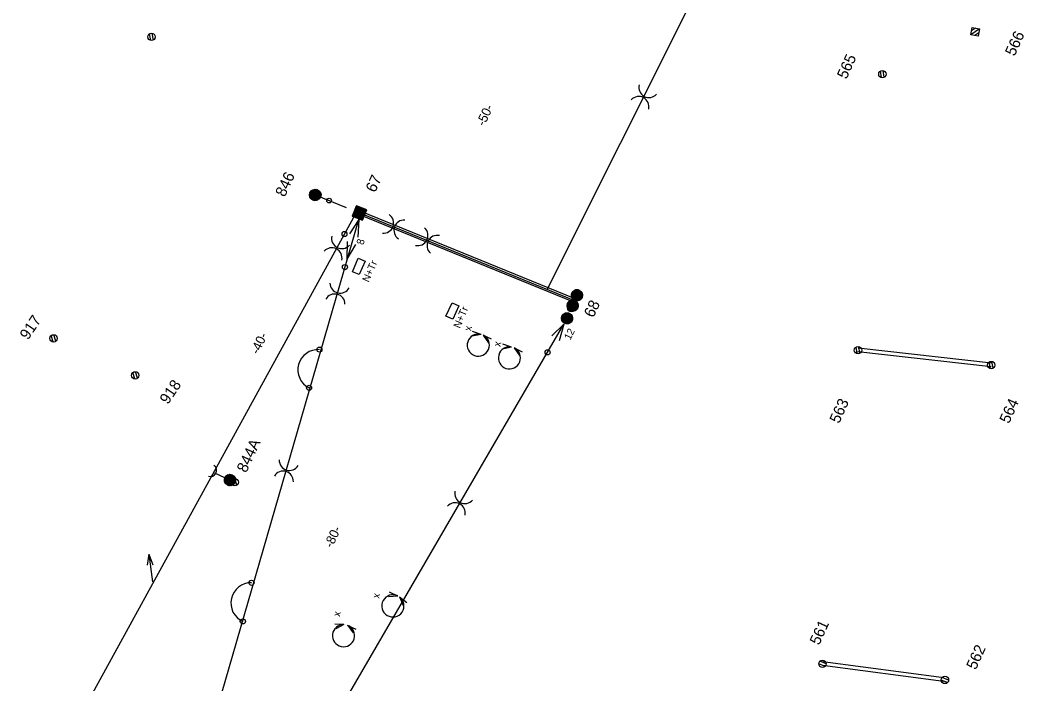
# Model space of a CAD drawing. Extents: x -595867 to -593796, y -1159595 to -1157495.
# Drawn here: x -594787.7 to -594651.8, y -1158117.2 to -1158027.2 of the extents above; entities that cross this region are included whole.
import ezdxf

# ---------------------------------------------------------------- set-up
doc = ezdxf.new("R2010")
doc.units = 0
for name, color, linetype in [('BVK_kanalizace_destova_nova', 7, 'Continuous'), ('BVK_kanalizace_jednotna_nova', 7, 'Continuous'), ('CD Telematika_novy', 7, 'Continuous')]:
    doc.layers.add(name, color=color, linetype=linetype)

# ---------------------------------------------------------------- blocks, each defined once
blk = doc.blocks.new('st_bp')
for p, q in [((0.0075, 0.0075), (-0.0075, 0.0075)), ((-0.0075, 0.0075), (-0.0075, -0.0075)), ((-0.0075, -0.0075), (0.0075, 0.0075)), ((-0.0075, -0.0071), (0.0071, 0.0075)), ((-0.0075, -0.0067), (0.0067, 0.0075)), ((-0.0075, -0.0062), (0.0062, 0.0075)), ((-0.0075, -0.0058), (0.0058, 0.0075)), ((-0.0075, -0.0054), (0.0054, 0.0075)), ((-0.0075, -0.005), (0.005, 0.0075)), ((-0.0075, -0.0045), (0.0045, 0.0075)), ((-0.0075, -0.0041), (0.0041, 0.0075)), ((-0.0075, -0.0037), (0.0037, 0.0075)), ((-0.0075, -0.0033), (0.0033, 0.0075)), ((-0.0075, -0.0028), (0.0028, 0.0075)), ((-0.0075, -0.0024), (0.0024, 0.0075)), ((-0.0075, -0.002), (0.002, 0.0075)), ((-0.0075, -0.0016), (0.0016, 0.0075)), ((-0.0075, -0.0011), (0.0011, 0.0075)), ((-0.0075, -0.0007), (0.0007, 0.0075)), ((-0.0075, -0.0003), (0.0003, 0.0075)), ((-0.0075, 0.0001), (-0.0001, 0.0075)), ((-0.0075, 0.0006), (-0.0006, 0.0075)), ((-0.0075, 0.001), (-0.001, 0.0075)), ((-0.0075, 0.0014), (-0.0014, 0.0075)), ((-0.0075, 0.0018), (-0.0018, 0.0075)), ((-0.0075, 0.0023), (-0.0023, 0.0075)), ((-0.0075, 0.0027), (-0.0027, 0.0075)), ((-0.0075, 0.0031), (-0.0031, 0.0075)), ((-0.0075, 0.0035), (-0.0035, 0.0075)), ((-0.0075, 0.004), (-0.004, 0.0075)), ((-0.0075, 0.0044), (-0.0044, 0.0075)), ((-0.0075, 0.0048), (-0.0048, 0.0075)), ((-0.0075, 0.0052), (-0.0052, 0.0075)), ((-0.0075, 0.0057), (-0.0057, 0.0075)), ((-0.0075, 0.0061), (-0.0061, 0.0075)), ((-0.0075, 0.0065), (-0.0065, 0.0075)), ((-0.0075, 0.0069), (-0.0069, 0.0075)), ((-0.0075, 0.0073), (-0.0073, 0.0075)), ((-0.0071, -0.0075), (0.0075, 0.0071)), ((-0.0067, -0.0075), (0.0075, 0.0067)), ((-0.0062, -0.0075), (0.0075, 0.0062)), ((-0.0058, -0.0075), (0.0075, 0.0058)), ((-0.0054, -0.0075), (0.0075, 0.0054)), ((-0.005, -0.0075), (0.0075, 0.005)), ((-0.0045, -0.0075), (0.0075, 0.0045)), ((-0.0041, -0.0075), (0.0075, 0.0041)), ((-0.0037, -0.0075), (0.0075, 0.0037)), ((-0.0033, -0.0075), (0.0075, 0.0033)), ((-0.0028, -0.0075), (0.0075, 0.0028)), ((-0.0024, -0.0075), (0.0075, 0.0024)), ((-0.002, -0.0075), (0.0075, 0.002)), ((-0.0016, -0.0075), (0.0075, 0.0016)), ((-0.0011, -0.0075), (0.0075, 0.0011)), ((-0.0007, -0.0075), (0.0075, 0.0007)), ((-0.0003, -0.0075), (0.0075, 0.0003)), ((0.0075, -0.0075), (0.0075, 0.0075)), ((-0.0075, -0.0075), (0.0075, -0.0075)), ((0.0001, -0.0075), (0.0075, -0.0001)), ((0.0006, -0.0075), (0.0075, -0.0006)), ((0.001, -0.0075), (0.0075, -0.001)), ((0.0014, -0.0075), (0.0075, -0.0014)), ((0.0018, -0.0075), (0.0075, -0.0018)), ((0.0023, -0.0075), (0.0075, -0.0023)), ((0.0027, -0.0075), (0.0075, -0.0027)), ((0.0031, -0.0075), (0.0075, -0.0031)), ((0.0035, -0.0075), (0.0075, -0.0035)), ((0.004, -0.0075), (0.0075, -0.004)), ((0.0044, -0.0075), (0.0075, -0.0044)), ((0.0048, -0.0075), (0.0075, -0.0048)), ((0.0052, -0.0075), (0.0075, -0.0052)), ((0.0057, -0.0075), (0.0075, -0.0057)), ((0.0061, -0.0075), (0.0075, -0.0061)), ((0.0065, -0.0075), (0.0075, -0.0065)), ((0.0069, -0.0075), (0.0075, -0.0069)), ((0.0073, -0.0075), (0.0075, -0.0073))]:
    blk.add_line(p, q)
blk = doc.blocks.new('st_tecka')
blk.add_circle((0, 0), 0.00314)
blk = doc.blocks.new('st_1t')
for points in [[(-0.0074, 0.0007), (0.0028, 0.0069), (0.0036, 0.0066), (-0.0075, -0.0002)], [(-0.0075, -0.0002), (0.0036, 0.0066), (0.0044, 0.006), (-0.0074, -0.001)], [(-0.0073, 0.0016), (0.0019, 0.0072), (0.0028, 0.0069), (-0.0074, 0.0007)], [(-0.0074, -0.001), (0.0044, 0.006), (0.0052, 0.0054), (-0.0072, -0.0019)], [(-0.0071, 0.0022), (0.0006, 0.0074), (0.0019, 0.0072), (-0.0073, 0.0016)], [(-0.0072, -0.0019), (0.0052, 0.0054), (0.0059, 0.0046), (-0.0069, -0.003)], [(-0.0069, 0.0029), (-0.0001, 0.0075), (0.0006, 0.0074), (-0.0071, 0.0022)], [(-0.0067, 0.0033), (-0.0015, 0.0073), (-0.0001, 0.0075), (-0.0069, 0.0029)], [(-0.0069, -0.003), (0.0059, 0.0046), (0.0067, 0.0034), (-0.0064, -0.0039)], [(-0.0063, 0.004), (-0.0022, 0.0071), (-0.0015, 0.0073), (-0.0067, 0.0033)], [(-0.0064, -0.0039), (0.0067, 0.0034), (0.0071, 0.0022), (-0.0057, -0.0049)], [(-0.0058, 0.0047), (-0.0032, 0.0068), (-0.0022, 0.0071), (-0.0063, 0.004)], [(-0.0053, 0.0053), (-0.0041, 0.0062), (-0.0032, 0.0068), (-0.0058, 0.0047)], [(-0.0057, -0.0049), (0.0071, 0.0022), (0.0074, 0.0011), (-0.0049, -0.0056)], [(-0.0049, -0.0056), (0.0074, 0.0011), (0.0075, -0.0004), (-0.004, -0.0063)], [(-0.004, -0.0063), (0.0075, -0.0004), (0.0073, -0.0017), (-0.0032, -0.0068)], [(-0.0032, -0.0068), (0.0073, -0.0017), (0.007, -0.0027), (-0.0021, -0.0072)], [(-0.0021, -0.0072), (0.007, -0.0027), (0.0065, -0.0037), (-0.0011, -0.0074)], [(-0.0011, -0.0074), (0.0065, -0.0037), (0.0059, -0.0046), (-0.0005, -0.0075)], [(-0.0005, -0.0075), (0.0059, -0.0046), (0.0054, -0.0052), (0.0004, -0.0075)], [(0.0004, -0.0075), (0.0054, -0.0052), (0.0045, -0.006), (0.0014, -0.0074)], [(0.0014, -0.0074), (0.0045, -0.006), (0.0038, -0.0064), (0.0025, -0.007)], [(0.0025, -0.007), (0.0038, -0.0064), (0.0029, -0.0069), (0.0029, -0.0069)]]:
    blk.add_lwpolyline(points, close=True)
blk.add_circle((0, 0), 0.0075)
blk = doc.blocks.new('st1k_1t')
blk.add_line((0, 0), (0.0453, 0))
blk.add_blockref('st_1t', (0, 0))
at = {"rotation": 90}
blk.add_blockref('st_tecka', (0.0205, 0), dxfattribs=at)
blk = doc.blocks.new('st_2t')
for points in [[(-0.0077, 0.0091), (0.0015, 0.0147), (0.0025, 0.0144), (-0.0078, 0.0082)], [(-0.0078, 0.0082), (0.0025, 0.0144), (0.0032, 0.014), (-0.0078, 0.0072)], [(-0.0078, 0.0072), (0.0032, 0.014), (0.004, 0.0135), (-0.0078, 0.0065)], [(-0.0075, 0.0097), (0.0002, 0.0149), (0.0015, 0.0147), (-0.0077, 0.0091)], [(-0.0073, 0.0104), (-0.0005, 0.015), (0.0002, 0.0149), (-0.0075, 0.0097)], [(-0.0071, 0.0108), (-0.0019, 0.0148), (-0.0005, 0.015), (-0.0073, 0.0104)], [(-0.0066, 0.0115), (-0.0026, 0.0146), (-0.0019, 0.0148), (-0.0071, 0.0108)], [(-0.0062, 0.0122), (-0.0035, 0.0142), (-0.0026, 0.0146), (-0.0066, 0.0115)], [(-0.0056, 0.0128), (-0.0045, 0.0137), (-0.0035, 0.0142), (-0.0062, 0.0122)], [(-0.0078, 0.0065), (0.004, 0.0135), (0.0048, 0.0129), (-0.0076, 0.0056)], [(-0.0076, 0.0056), (0.0048, 0.0129), (0.0055, 0.0121), (-0.0073, 0.0044)], [(-0.0073, 0.0044), (0.0055, 0.0121), (0.0063, 0.0109), (-0.0068, 0.0036)], [(-0.0068, 0.0036), (0.0063, 0.0109), (0.0067, 0.0097), (-0.006, 0.0026)], [(-0.006, 0.0026), (0.0067, 0.0097), (0.007, 0.0086), (-0.0052, 0.0018)], [(-0.0052, 0.0018), (0.007, 0.0086), (0.0071, 0.0071), (-0.0044, 0.0012)], [(-0.0044, 0.0012), (0.0071, 0.0071), (0.0069, 0.0057), (-0.0035, 0.0007)], [(-0.0035, 0.0007), (0.0069, 0.0057), (0.0066, 0.0047), (-0.0024, 0.0003)], [(-0.0024, 0.0003), (0.0066, 0.0047), (0.0061, 0.0038), (-0.0015, 0.0001)], [(-0.0015, 0.0001), (0.0061, 0.0038), (0.0055, 0.0029), (-0.0009, 0)], [(-0.0009, 0), (0.0055, 0.0029), (0.005, 0.0022), (0, 0)], [(0, 0), (0.005, 0.0022), (0.0041, 0.0015), (0.001, 0.0001)], [(0.001, 0.0001), (0.0041, 0.0015), (0.0035, 0.001), (0.0021, 0.0004)], [(0.0021, 0.0004), (0.0035, 0.001), (0.0026, 0.0006), (0.0026, 0.0005)], [(-0.0077, -0.0059), (0.0015, -0.0003), (0.0025, -0.0006), (-0.0078, -0.0068)], [(-0.0078, -0.0068), (0.0025, -0.0006), (0.0032, -0.001), (-0.0078, -0.0078)], [(-0.0078, -0.0078), (0.0032, -0.001), (0.004, -0.0015), (-0.0078, -0.0085)], [(-0.0078, -0.0085), (0.004, -0.0015), (0.0048, -0.0021), (-0.0076, -0.0094)], [(-0.0075, -0.0053), (0.0002, -0.0001), (0.0015, -0.0003), (-0.0077, -0.0059)], [(-0.0076, -0.0094), (0.0048, -0.0021), (0.0055, -0.0029), (-0.0073, -0.0106)], [(-0.0073, -0.0046), (-0.0005, 0), (0.0002, -0.0001), (-0.0075, -0.0053)], [(-0.0071, -0.0042), (-0.0019, -0.0002), (-0.0005, 0), (-0.0073, -0.0046)], [(-0.0073, -0.0106), (0.0055, -0.0029), (0.0063, -0.0041), (-0.0068, -0.0114)], [(-0.0066, -0.0035), (-0.0026, -0.0004), (-0.0019, -0.0002), (-0.0071, -0.0042)], [(-0.0068, -0.0114), (0.0063, -0.0041), (0.0067, -0.0053), (-0.006, -0.0124)], [(-0.0062, -0.0028), (-0.0035, -0.0008), (-0.0026, -0.0004), (-0.0066, -0.0035)], [(-0.0056, -0.0022), (-0.0045, -0.0013), (-0.0035, -0.0008), (-0.0062, -0.0028)], [(-0.006, -0.0124), (0.0067, -0.0053), (0.007, -0.0064), (-0.0052, -0.0132)], [(-0.0052, -0.0132), (0.007, -0.0064), (0.0071, -0.0079), (-0.0044, -0.0138)], [(-0.0044, -0.0138), (0.0071, -0.0079), (0.0069, -0.0093), (-0.0035, -0.0143)], [(-0.0035, -0.0143), (0.0069, -0.0093), (0.0066, -0.0103), (-0.0024, -0.0147)], [(-0.0024, -0.0147), (0.0066, -0.0103), (0.0061, -0.0112), (-0.0015, -0.0149)], [(-0.0015, -0.0149), (0.0061, -0.0112), (0.0055, -0.0121), (-0.0009, -0.015)], [(-0.0009, -0.015), (0.0055, -0.0121), (0.005, -0.0128), (0, -0.015)], [(0, -0.015), (0.005, -0.0128), (0.0041, -0.0135), (0.001, -0.0149)], [(0.001, -0.0149), (0.0041, -0.0135), (0.0035, -0.014), (0.0021, -0.0146)], [(0.0021, -0.0146), (0.0035, -0.014), (0.0026, -0.0144), (0.0026, -0.0145)]]:
    blk.add_lwpolyline(points, close=True)
for centre in [(-0.0004, 0.0075), (-0.0004, -0.0075)]:
    blk.add_circle(centre, 0.0075)
blk = doc.blocks.new('pol_izol')
for centre, start, end in [((-0.0148, 0), 284.4047, 75.5953), ((0.0148, 0), 104.4047, 255.5953)]:
    blk.add_arc(centre, 0.0138, start, end)
blk = doc.blocks.new('kotv_tecka')
blk.add_circle((0, 0), 0.00345)
blk = doc.blocks.new('kotv_polok')
for p, q in [((-0.0558, 0), (-0.0328, 0.0065)), ((-0.0558, 0), (-0.0336, -0.0056)), ((0, 0), (-0.023, -0.0056))]:
    blk.add_line(p, q)
blk.add_lwpolyline([(0, 0), (-0.0221, 0.0064)])
blk.add_blockref('kotv_tecka', (-0.067, 0))
blk = doc.blocks.new('pol_proplan')
blk.add_arc((0.0268, -0.0054), 0.0274, 11.4341, 168.5659)
for p in [(0, 0), (0.0536, 0)]:
    blk.add_blockref('kotv_tecka', p)
blk = doc.blocks.new('kotv_pev')
blk.add_line((0, 0), (-0.023, -0.0056))
blk.add_lwpolyline([(0, 0), (-0.0221, 0.0064)])
blk.add_blockref('kotv_tecka', (-0.0442, 0))
blk = doc.blocks.new('pol_pevbod')
for q in [(0, 0), (0.0163, 0.0168), (0.0204, 0.0101)]:
    blk.add_line((0.0305, 0.0219), q)
blk = doc.blocks.new('pol_sipka2')
for q in [(0.0123, 0.003), (0.0118, -0.0034)]:
    blk.add_line((0, 0), q)
blk = doc.blocks.new('pol_sjsp')
for p, q in [((-0.01, 0.005), (0.01, 0.005)), ((-0.01, -0.005), (-0.01, 0.005)), ((0.01, 0.005), (0.01, -0.005)), ((0.01, -0.005), (-0.01, -0.005))]:
    blk.add_line(p, q)

msp = doc.modelspace()

# ---------------------------------------------------------------- linework, layer by layer
at = {"layer": 'BVK_kanalizace_destova_nova'}
for p, q in [((-594716.34, -1158063.66), (-594693.63, -1158018.29)), ((-594780.3, -1158122.8), (-594742.55, -1158053.94)), ((-594741.78, -1158053.36), (-594712.66, -1158065.21)), ((-594763.76, -1158129.95), (-594741.89, -1158054.27)), ((-594752.74, -1158134.87), (-594714.09, -1158068.43)), ((-594759.35, -1158089.55), (-594761.36, -1158088.6))]:
    msp.add_line(p, q, dxfattribs=at)
for centre, radius, start, end in [((-594725.69, -1158071.27), 1.5, 75.6521, 64.479), ((-594721.48, -1158073), 1.5, 78.265, 65.3517), ((-594761.96, -1158088.25), 0.835, 251.6066, 55.2681), ((-594737.26, -1158106.6), 1.5, 63.4805, 53.6942), ((-594743.94, -1158110.63), 1.5, 87.9769, 68.276)]:
    msp.add_arc(centre, radius, start, end, dxfattribs=at)
at = {"layer": 'BVK_kanalizace_jednotna_nova'}
for p, q in [((-594770.05, -1158030), (-594770.21, -1158029.1)), ((-594769.68, -1158029.95), (-594769.84, -1158029.03)), ((-594657.83, -1158028.44), (-594659, -1158029.23)), ((-594658.35, -1158028.33), (-594658.9, -1158028.71)), ((-594657.93, -1158028.96), (-594658.48, -1158029.33)), ((-594671.09, -1158035.04), (-594671.25, -1158034.14)), ((-594670.72, -1158034.99), (-594670.88, -1158034.07)), ((-594747.53, -1158051.37), (-594747.79, -1158050.5)), ((-594747.16, -1158051.27), (-594747.43, -1158050.39)), ((-594741.12, -1158053.12), (-594742.44, -1158053.61)), ((-594741.6, -1158052.89), (-594742.22, -1158053.13)), ((-594741.34, -1158053.6), (-594741.96, -1158053.83)), ((-594712.58, -1158065.22), (-594712.74, -1158064.32)), ((-594712.21, -1158065.17), (-594712.38, -1158064.25)), ((-594713.2, -1158066.74), (-594713.36, -1158065.84)), ((-594712.98, -1158066.14), (-594713.14, -1158065.24)), ((-594712.83, -1158066.69), (-594712.99, -1158065.77)), ((-594712.61, -1158066.08), (-594712.78, -1158065.17)), ((-594783.26, -1158070.85), (-594783.52, -1158069.98)), ((-594782.89, -1158070.75), (-594783.16, -1158069.86)), ((-594674.39, -1158072.43), (-594674.55, -1158071.53)), ((-594674.02, -1158072.37), (-594674.18, -1158071.46)), ((-594656.35, -1158074.45), (-594656.51, -1158073.55)), ((-594655.98, -1158074.39), (-594656.14, -1158073.48)), ((-594772.2, -1158075.86), (-594772.46, -1158074.99)), ((-594771.83, -1158075.76), (-594772.1, -1158074.88)), ((-594758.73, -1158090.33), (-594759, -1158089.46)), ((-594758.37, -1158090.23), (-594758.64, -1158089.34)), ((-594678.73, -1158114.79), (-594679.58, -1158114.45)), ((-594678.58, -1158114.45), (-594679.44, -1158114.1)), ((-594662.01, -1158116.64), (-594662.87, -1158116.29)), ((-594662.16, -1158116.98), (-594663.01, -1158116.64))]:
    msp.add_line(p, q, dxfattribs=at)
for points in [[(-594658.02, -1158029.42), (-594659, -1158029.22), (-594658.81, -1158028.24), (-594657.83, -1158028.43)], [(-594741.53, -1158054.02), (-594742.44, -1158053.6), (-594742.03, -1158052.7), (-594741.12, -1158053.11)]]:
    msp.add_lwpolyline(points, close=True, dxfattribs=at)
for points in [[(-594658.02, -1158029.42), (-594659, -1158029.22), (-594658.81, -1158028.24), (-594657.83, -1158028.43), (-594658.02, -1158029.42)], [(-594741.53, -1158054.02), (-594742.44, -1158053.6), (-594742.03, -1158052.7), (-594741.12, -1158053.11), (-594741.53, -1158054.02)], [(-594712.75, -1158065.44), (-594741.87, -1158053.59)], [(-594712.56, -1158064.98), (-594741.69, -1158053.13)], [(-594656.27, -1158074.22), (-594674.31, -1158072.2)], [(-594656.21, -1158073.72), (-594674.25, -1158071.7)], [(-594662.69, -1158116.82), (-594679.11, -1158114.69)], [(-594662.65, -1158116.34), (-594679.05, -1158114.19)]]:
    msp.add_lwpolyline(points, dxfattribs=at)
for centre in [(-594769.94, -1158029.52), (-594769.94, -1158029.52), (-594670.98, -1158034.56), (-594670.98, -1158034.56), (-594747.47, -1158050.88), (-594747.47, -1158050.88), (-594712.47, -1158064.74), (-594712.47, -1158064.74), (-594713.09, -1158066.26), (-594713.09, -1158066.26), (-594712.87, -1158065.66), (-594712.87, -1158065.66), (-594783.2, -1158070.36), (-594783.2, -1158070.36), (-594674.28, -1158071.95), (-594674.28, -1158071.95), (-594656.24, -1158073.97), (-594656.24, -1158073.97), (-594772.14, -1158075.37), (-594772.14, -1158075.37), (-594758.68, -1158089.84), (-594758.68, -1158089.84), (-594679.08, -1158114.44), (-594679.08, -1158114.44), (-594662.51, -1158116.63), (-594662.51, -1158116.63)]:
    msp.add_circle(centre, 0.5, dxfattribs=at)

# ---------------------------------------------------------------- block references
at = {"layer": 'BVK_kanalizace_destova_nova'}
for name, p, xscale, yscale, rotation in [('pol_izol', (-594703.27, -1158037.66), 100.00000000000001, 99.99999999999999, 61.94506563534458), ('st1k_1t', (-594747.79, -1158050.92), 100, 100, -22.17602714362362), ('st_bp', (-594741.78, -1158053.36), 100.00000000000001, 100, -21.47464092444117), ('pol_izol', (-594737.14, -1158055.23), 100, 99.99999999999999, -19.390806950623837), ('kotv_polok', (-594741.89, -1158054.27), 100, 99.99999999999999, 73.87588055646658), ('pol_izol', (-594744.85, -1158058.14), 100, 100, 63.029073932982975), ('kotv_tecka', (-594743.81, -1158056.22), 100.00000000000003, 99.99999999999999, 79.51685128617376), ('pol_izol', (-594732.57, -1158057.1), 100, 100, -27.31603233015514), ('pol_izol', (-594744.76, -1158064.29), 100, 100, 75.70598100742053), ('st_2t', (-594712.66, -1158065.21), 100.00000000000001, 99.99999999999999, 157.6710196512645), ('st_1t', (-594713.67, -1158067.64), 100.00000000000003, 99.99999999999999, 79.51685128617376), ('kotv_pev', (-594714.09, -1158068.43), 100, 100, 59.8138508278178), ('pol_sipka2', (-594725.32, -1158069.82), 100, 99.99999999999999, 177.96781294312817), ('pol_sipka2', (-594725.04, -1158069.92), 99.99999999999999, -100.00000000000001, -41.28973469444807), ('pol_proplan', (-594748.6, -1158077.06), 100.00000000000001, 100, 74.86719705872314), ('pol_sipka2', (-594721.18, -1158071.53), 100.00000000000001, 99.99999999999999, 178.58126581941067), ('pol_sipka2', (-594720.85, -1158071.64), 100, -100, -41.9329323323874), ('pol_izol', (-594751.69, -1158088.3), 100, 99.99999999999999, 73.34797923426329), ('st_1t', (-594759.32, -1158089.55), 100.00000000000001, 100, 1), ('pol_izol', (-594728.17, -1158092.68), 100, 100, 63.564354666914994), ('pol_pevbod', (-594769.8, -1158103.32), 100, 100, 62.12956287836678), ('pol_proplan', (-594757.57, -1158108.7), 99.99999999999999, 100, 77.37936445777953), ('pol_sipka2', (-594736.59, -1158105.26), 99.99999999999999, 100, 170.93181055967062), ('pol_sipka2', (-594736.37, -1158105.39), 100, -100, -52.49270793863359), ('pol_sipka2', (-594743.88, -1158109.13), 99.99999999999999, 100, -165.72393793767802), ('pol_sipka2', (-594743.38, -1158109.24), 100, -99.99999999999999, -39.860744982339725)]:
    msp.add_blockref(name, p, dxfattribs=dict(at, xscale=xscale, yscale=yscale, rotation=rotation))
at = {"layer": 'CD Telematika_novy'}
for p, xscale, yscale, rotation in [((-594741.88, -1158060.61), 100, 100, 66.41014899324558), ((-594729.2, -1158066.65), 100.00000000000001, 99.99999999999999, 65.41114768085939)]:
    msp.add_blockref('pol_sjsp', p, dxfattribs=dict(at, xscale=xscale, yscale=yscale, rotation=rotation))

# ---------------------------------------------------------------- texts
at = {"layer": 'BVK_kanalizace_destova_nova'}
for s, height, rotation, p in [('-50-', 1.25, 65.0264, (-594724.88, -1158041.71)), ('846', 1.5, 65.0264, (-594751.9, -1158051.3)), ('67', 1.5, 65.0264, (-594739.67, -1158050.7)), ('8', 1, 74.9481, (-594741.25, -1158057.76)), ('68', 1.5, 65.0264, (-594710.11, -1158067.65)), ('x', 1, 77.795, (-594726.67, -1158069.43)), ('-40-', 1.25, 65.0264, (-594755.46, -1158072.61)), ('12', 1, 63.2911, (-594713.25, -1158070.66)), ('x', 1, 77.795, (-594722.71, -1158071.55)), ('844A', 1.5, 65.0264, (-594757.12, -1158088.66)), ('-80-', 1.25, 65.0264, (-594745.49, -1158098.84)), ('x', 1, 77.795, (-594739.11, -1158105.65)), ('x', 1, 77.795, (-594744.43, -1158108.11))]:
    msp.add_text(s, height=height, rotation=rotation, dxfattribs=at).set_placement(p)
at = {"layer": 'BVK_kanalizace_jednotna_nova'}
for s, rotation, p in [('566', 65.5984, (-594653.08, -1158032.22)), ('565', 65.5984, (-594675.84, -1158035.34)), ('917', 56, (-594786.66, -1158070.66)), ('918', 56, (-594767.71, -1158079.39)), ('563', 65.5984, (-594676.85, -1158081.99)), ('564', 65.5984, (-594653.84, -1158082)), ('561', 65.5984, (-594679.54, -1158112.01)), ('562', 65.5984, (-594658.33, -1158115.35))]:
    msp.add_text(s, height=1.5, rotation=rotation, dxfattribs=at).set_placement(p)
at = {"layer": 'CD Telematika_novy'}
for rotation, p in [(66.2941, (-594740.54, -1158062.83)), (67.5034, (-594728.18, -1158069.08))]:
    msp.add_text('N+Tr', height=1, rotation=rotation, dxfattribs=at).set_placement(p)

doc.saveas('drawing.dxf')
